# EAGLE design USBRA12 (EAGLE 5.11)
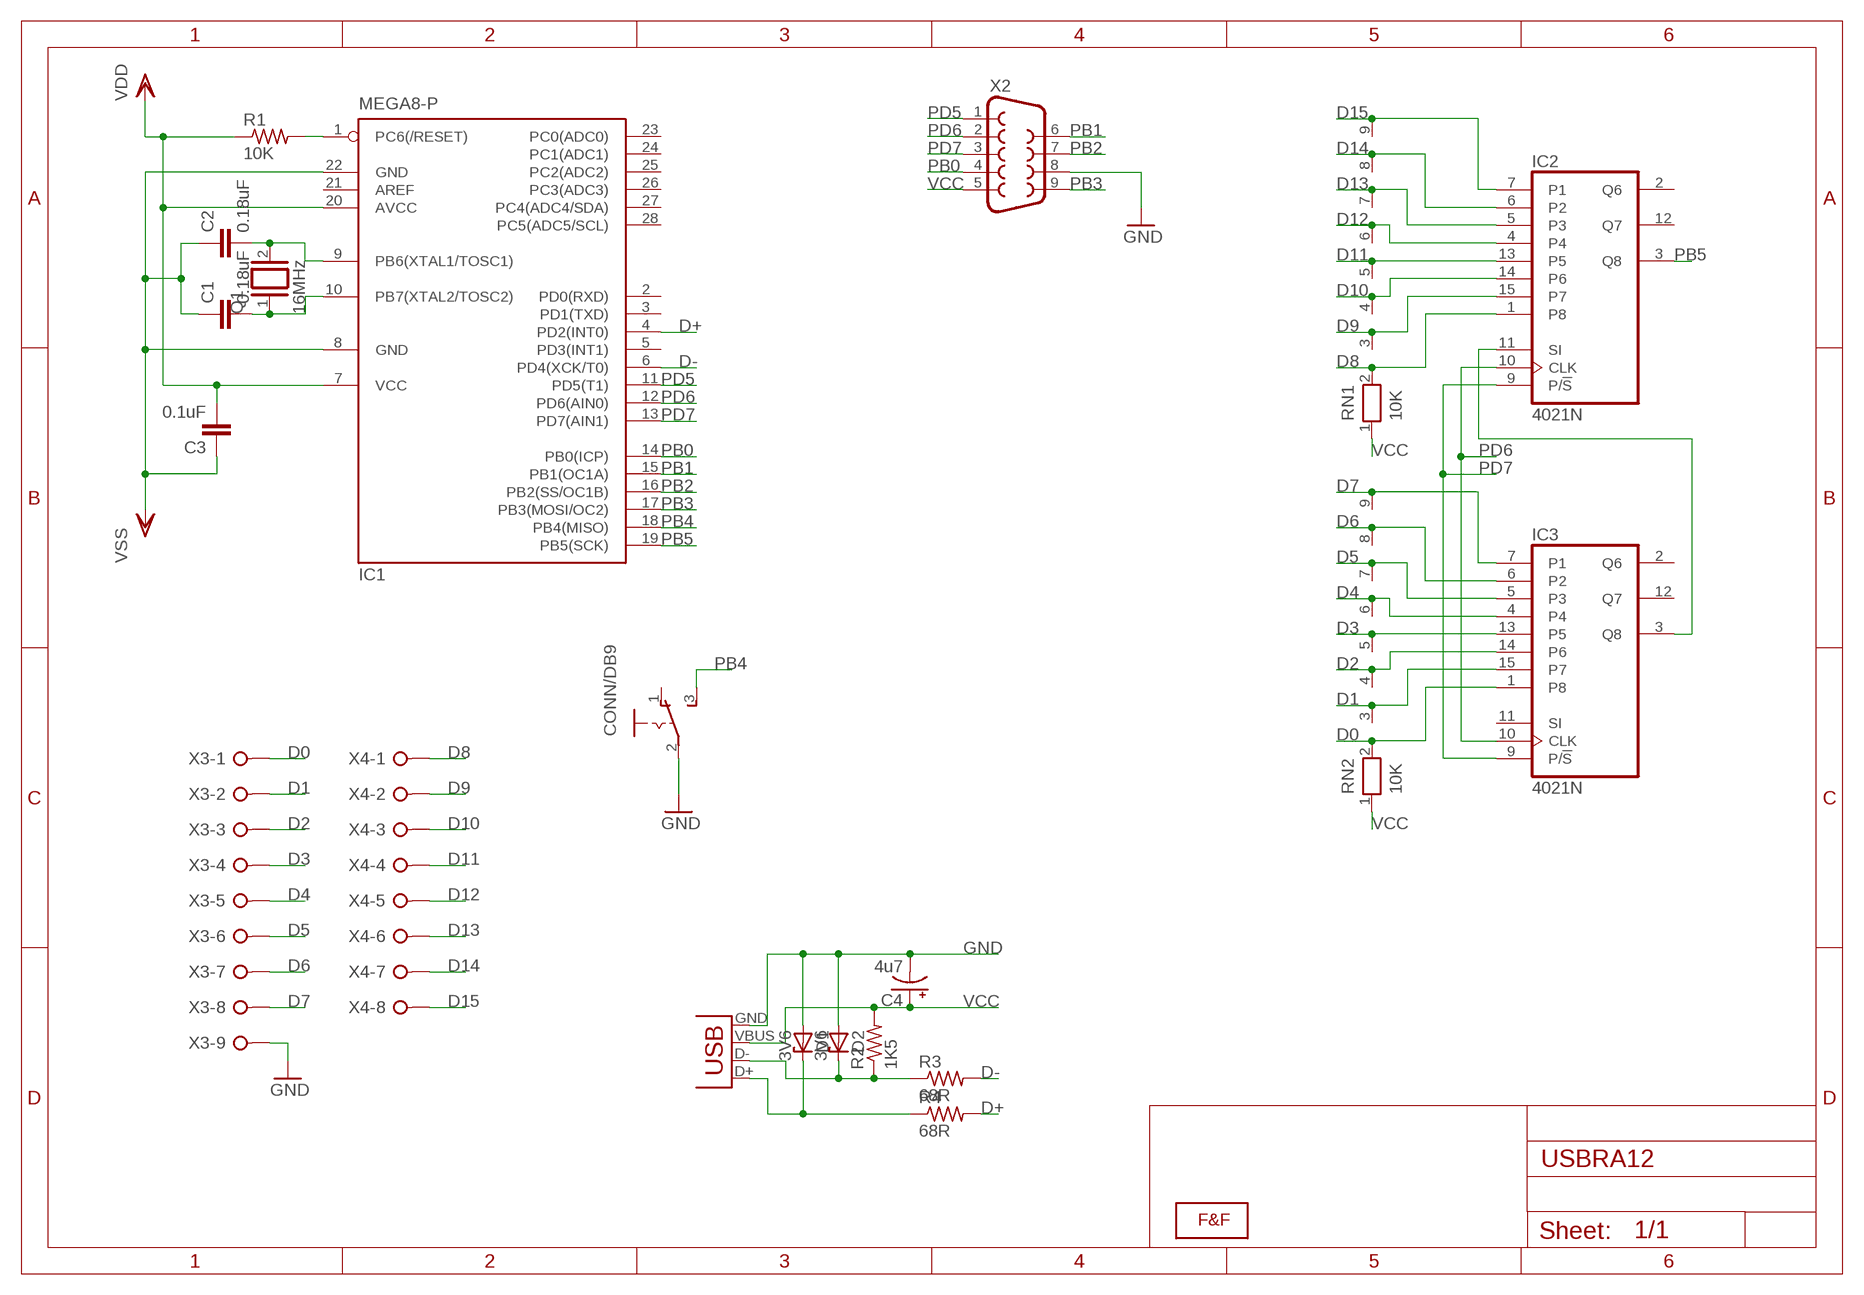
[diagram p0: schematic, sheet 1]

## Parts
C1  0.18uF  CAPPTH  [CAP-PTH-SMALL]
C2  0.18uF  CAPPTH  [CAP-PTH-SMALL]
C3  0.1uF  CAPPTH  [CAP-PTH-SMALL]
C4  4u7  CPOL-USE2.5-6  [E2,5-6]
CONN/DB9  CHAVE  [CHAVE]
D1  3V6  ZENER-DIODEF126-12  [F126Z12]
D2  3V6  ZENER-DIODEF126-12  [F126Z12]
IC1  MEGA8-P  [DIL28-3]
IC2  4021N  [DIL16]
IC3  4021N  [DIL16]
Q1  16MHz  XTAL/S  [QS]
R1  10K  R-US_0207/10  [0207/10]
R2  1K5  R-US_0207/10  [0207/10]
R3  68R  R-US_0207/10  [0207/10]
R4  68R  R-US_0207/10  [0207/10]
RN1  10K  RN08  [RN-9]
RN2  10K  RN08  [RN-9]
U$1  LOGOLOGO_WITHOUT_SMOKE_BIG  [LOGO2_BIG]
X1  USBPTH  [USB-B-PTH]
X2  DB9MALE  [DB9_MALE]
X3  W237-09P  [W237-9P]
X4  W237-08P  [W237-8P]

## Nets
D0: IC3.1(P8) RN2.2 X3.1
D1: IC3.15(P7) RN2.3 X3.2
D2: IC3.14(P6) RN2.4 X3.3
D3: IC3.13(P5) RN2.5 X3.4
D4: IC3.4 RN2.6 X3.5
D5: IC3.5(P3) RN2.7 X3.6
D6: IC3.6(P2) RN2.8 X3.7
D7: IC3.7(P1) RN2.9 X3.8
D8: IC2.1(P8) RN1.2 X4.1
D9: IC2.15(P7) RN1.3 X4.2
D10: IC2.14(P6) RN1.4 X4.3
D11: IC2.13(P5) RN1.5 X4.4
D12: IC2.4 RN1.6 X4.5
D13: IC2.5(P3) RN1.7 X4.6
D14: IC2.6(P2) RN1.8 X4.7
D15: IC2.7(P1) RN1.9 X4.8
D+: IC1.4(PD2(INT0)) R4.2
D-: IC1.6(PD4(XCK/T0)) R3.2
GND: C1.1 C2.1 C3.1 C4.- CONN/DB9.2(P) D1.A D2.A IC1.8(GND) IC1.22(GND) X1.GND X2.8 X3.9 ; supply symbol labelled VSS
N$1: IC1.1(PC6(/RESET)) R1.2
N$2: C2.2 IC1.9(PB6(XTAL1/TOSC1)) Q1.2
N$3: C1.2 IC1.10(PB7(XTAL2/TOSC2)) Q1.1
N$4: IC2.11(SI) IC3.3(Q8)
N$8: D1.C R4.1 X1.D+
N$9: D2.C R2.1 R3.1 X1.D-
PB0: IC1.14(PB0(ICP)) X2.4
PB1: IC1.15(PB1(OC1A)) X2.6
PB2: IC1.16(PB2(SS/OC1B)) X2.7
PB3: IC1.17(PB3(MOSI/OC2)) X2.9
PB4: CONN/DB9.3(S) IC1.18(PB4(MISO))
PB5: IC1.19(PB5(SCK)) IC2.3(Q8)
PD5: IC1.11(PD5(T1)) X2.1
PD6: IC1.12(PD6(AIN0)) IC2.10(CLK) IC3.10(CLK) X2.2
PD7: IC1.13(PD7(AIN1)) IC2.9(P/!S) IC3.9(P/!S) X2.3
VCC: C3.2 C4.+ IC1.7(VCC) IC1.20(AVCC) R1.1 R2.2 RN1.1 RN2.1 X1.VBUS X2.5 ; supply symbol labelled VDD
Unconnected: CONN/DB9.1(O) IC1.2(PD0(RXD)) IC1.3(PD1(TXD)) IC1.5(PD3(INT1)) IC1.21(AREF) IC1.23(PC0(ADC0)) IC1.24(PC1(ADC1)) IC1.25(PC2(ADC2)) IC1.26(PC3(ADC3)) IC1.27(PC4(ADC4/SDA)) IC1.28(PC5(ADC5/SCL)) IC2.2(Q6) IC2.12(Q7) IC3.2(Q6) IC3.11(SI) IC3.12(Q7)

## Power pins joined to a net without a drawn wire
GND: IC2.8(VSS) IC3.8(VSS)
VCC: IC2.16(VDD) IC3.16(VDD)

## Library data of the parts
C1-C3 = SparkFun:CAP: Capacitor
C4 = adafruit:CPOL-US: POLARIZED CAPACITOR, American symbol
CONN/DB9 = switch-fef:CHAVE: chave Verificar
D1 D2 = diode:ZENER-DIODE: Z-Diode
IC1 = atmel:MEGA8-P: MICROCONTROLLER 8 Kbytes FLASH, 1 kbytes SRAM, 512 bytes EEPROM, USART, 4-channel 10 bit ADC, 2-channel 8 bit ADC Pin compatible with Atmega48, ATMega88, ATMega168 Source: avr.lbr; OC_FARNELL: unknown; OC_NEWARK: unknown
IC2 IC3 = 40xx:4021: 8-bit static SHIFT REGISTER
Q1 = special:XTAL/S: CRYSTAL
R1-R4 = adafruit:R-US_: RESISTOR, American symbol
RN1 RN2 = resistor-net:RN08: RESISTOR NETWORK; OC_FARNELL: unknown; OC_NEWARK: unknown
U$1 = F&F:LOGO: Faísca e Fumaça Logo
X1 = SparkFun:USB: USB Connectors USB-B-PTH is fully proven SKU : PRT-00139 USB-miniB is fully proven SKU : PRT-00587 USB-A-PCB is untested. USB-A-H is throughly reviewed, but untested. Spark Fun Electronics SKU : PRT-00437 USB-B-SMT is throughly reviewed, but untested. Needs silkscreen touching up. USB-A-S has not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
X2 = SparkFun:DB9: DB9 Connector Standard DB9 (D-Sub 9) serial connector. Can be used for CAN bus as well as RS485 and RS232. Footprint production proven. Spark Fun Electronics SKU : PRT-00429
X3 = con-wago-508:W237-09P: WAGO SREW CLAMP; OC_FARNELL: unknown; OC_NEWARK: unknown
X4 = con-wago-508:W237-08P: WAGO SREW CLAMP; OC_FARNELL: unknown; OC_NEWARK: unknown

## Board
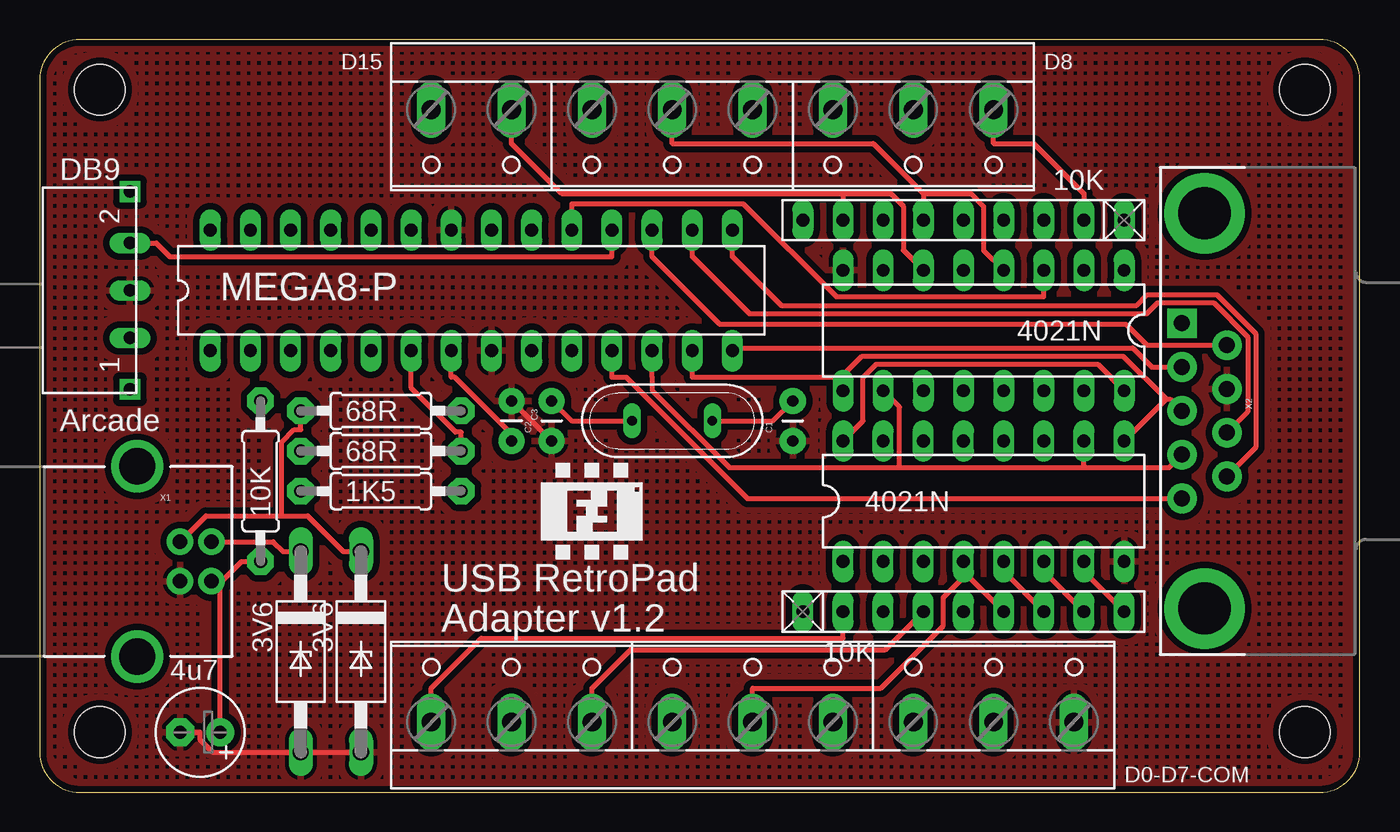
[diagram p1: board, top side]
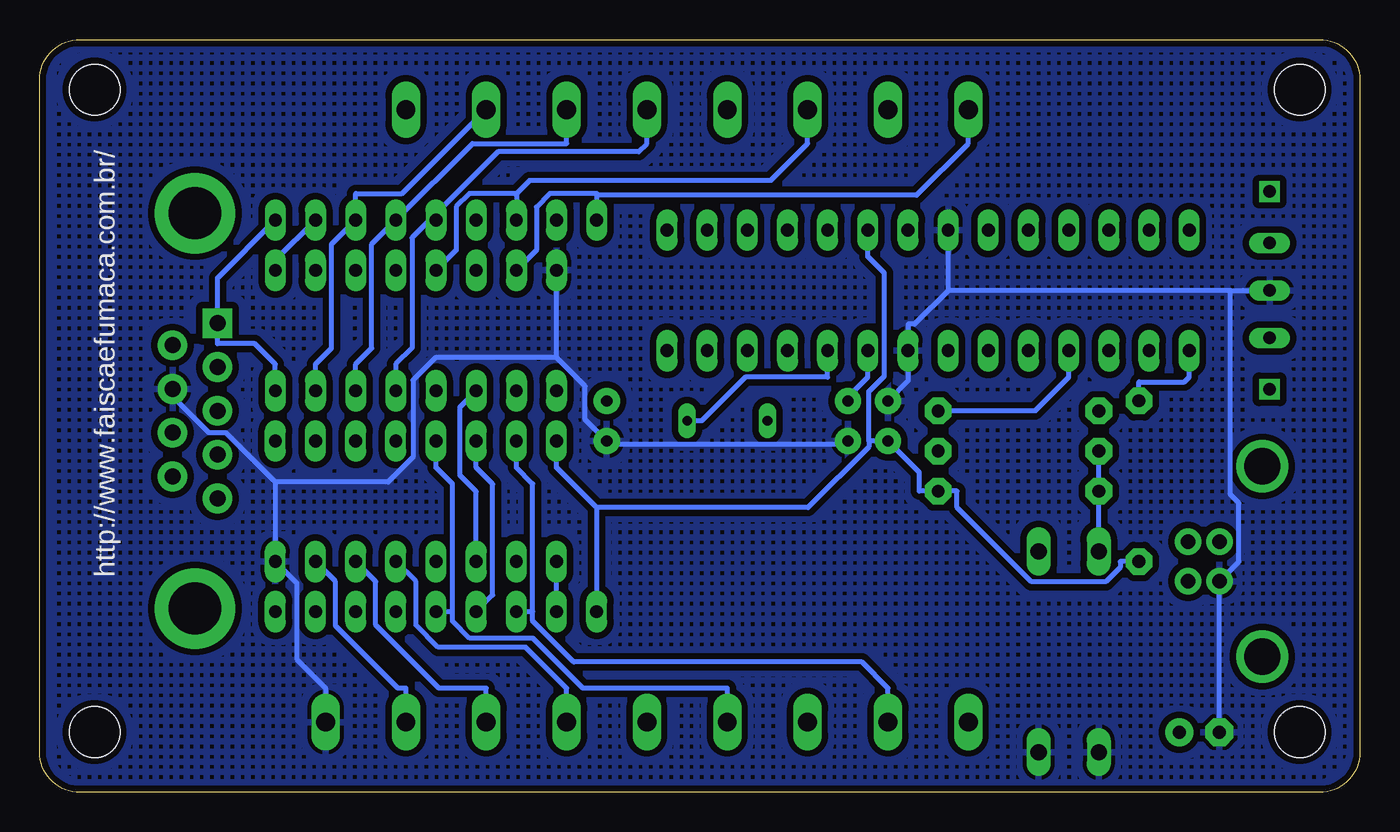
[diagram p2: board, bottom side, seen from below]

Size 83.49 x 47.62 mm. Coordinates in mm from the lower left corner, seen from the top.
Outline: 83.49,45.08 arc90 80.95,47.62 2.54,47.62 arc90 0,45.08 0,2.54 arc90 2.54,0 80.95,0 arc90 83.49,2.54 83.49,45.08
Copper layers (1*16): Top 0.035mm / dielectric 1.5mm / Bottom 0.035mm
Design rules "Fusion_eagle_rule_v1.1": minimum track width 6mil, minimum drill 12mil, track to track 6mil, track to pad 6mil, pad to pad 6mil, via to via 6mil, smd to smd 0mil, copper to edge 10mil, drill to drill 10mil, minimum pad ring 10mil, minimum via ring 6mil, stop-mask expansion 2mil, vias tented up to drill 100mil, thermal gap 10mil
Holes 3.2 mm at 3.81,44.45 3.81,3.81 80.01,44.45 80.01,3.81

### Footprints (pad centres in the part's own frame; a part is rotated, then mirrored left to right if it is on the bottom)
CAP-PTH-SMALL = drill 0.7 pad 1.651 round: 1 0,0; 2 2.54,0
E2,5-6 = drill 0.813 pad 1.778 round: + -1.27,0 | drill 0.813 pad 1.778 octagon: - 1.27,0
CHAVE = drill 0.8 long: 1 -3,0; 2 0,0; 3 3,0 | drill 0.8 square: P$1 -6.25,0; P$2 6.25,0
F126Z12 = drill 1.016 long: A 6.35,0; C -6.35,0
DIL28-3 = drill 0.813 long: 1 -16.51,-3.81; 2 -13.97,-3.81; 3 -11.43,-3.81; 4 -8.89,-3.81; 5 -6.35,-3.81; 6 -3.81,-3.81; 7 -1.27,-3.81; 8 1.27,-3.81; 9 3.81,-3.81; 10 6.35,-3.81; 11 8.89,-3.81; 12 11.43,-3.81; 13 13.97,-3.81; 14 16.51,-3.81; 15 16.51,3.81; 16 13.97,3.81; 17 11.43,3.81; 18 8.89,3.81; 19 6.35,3.81; 20 3.81,3.81; 21 1.27,3.81; 22 -1.27,3.81; 23 -3.81,3.81; 24 -6.35,3.81; 25 -8.89,3.81; 26 -11.43,3.81; 27 -13.97,3.81; 28 -16.51,3.81
DIL16 = drill 0.813 long: 1 -8.89,-3.81; 2 -6.35,-3.81; 3 -3.81,-3.81; 4 -1.27,-3.81; 5 1.27,-3.81; 6 3.81,-3.81; 7 6.35,-3.81; 8 8.89,-3.81; 9 8.89,3.81; 10 6.35,3.81; 11 3.81,3.81; 12 1.27,3.81; 13 -1.27,3.81; 14 -3.81,3.81; 15 -6.35,3.81; 16 -8.89,3.81
QS = drill 0.61 long: 1 -2.54,0; 2 2.54,0
0207/10 = drill 0.813 pad 1.676 octagon: 1 -5.08,0; 2 5.08,0
RN-9 = drill 0.813 long: 1 -10.16,0; 2 -7.62,0; 3 -5.08,0; 4 -2.54,0; 5 0,0; 6 2.54,0; 7 5.08,0; 8 7.62,0; 9 10.16,0
USB-B-PTH = drill 0.914 pad 1.676 round: D+ 0,1.25; D- 1.981,1.25; GND 0,-1.25; VBUS 1.981,-1.25 | drill 2.286 round: S1 -2.718,-6.02; S2 -2.718,6.02
DB9_MALE = drill 1.016 pad 1.88 round: 1 5.54,-1.42; 2 2.77,-1.42; 3 0,-1.42; 4 -2.77,-1.42; 6 4.15,1.42; 7 1.38,1.42; 8 -1.38,1.42; 9 -4.15,1.42 | drill 1.016 pad 1.88 square: 5 -5.54,-1.42 | drill 3.302 pad 5.08 round: G1 -12.5,0; G2 12.5,0
W237-9P = drill 1.194 long: 1 -20.32,-0.635; 2 -15.24,-0.635; 3 -10.16,-0.635; 4 -5.08,-0.635; 5 0,-0.635; 6 5.08,-0.635; 7 10.16,-0.635; 8 15.24,-0.635; 9 20.32,-0.635
W237-8P = drill 1.194 long: 1 -17.78,-0.635; 2 -12.7,-0.635; 3 -7.62,-0.635; 4 -2.54,-0.635; 5 2.54,-0.635; 6 7.62,-0.635; 7 12.7,-0.635; 8 17.78,-0.635

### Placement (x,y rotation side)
C1  47.62,22.23 90 top
C2  32.38,22.23 90 top
C3  29.84,24.77 270 top
C4  10.16,3.81 180 top
CONN/DB9  5.71,31.75 90 top
D1  20.32,8.89 270 top
D2  16.51,8.89 270 top
IC1  27.3,31.75 0 top
IC2  59.69,29.21 180 top
IC3  59.69,18.41 0 top
Q1  40.01,23.5 180 top
R1  13.97,19.68 90 top
R2  21.59,19.05 0 top
R3  21.59,21.59 0 top
R4  21.59,24.13 0 top
RN1  58.42,36.2 180 top
RN2  58.42,11.43 0 top
U$1  34.92,17.78 0 top
X1  8.89,14.61 0 top
X2  73.66,24.13 270 top
X3  45.09,5.08 0 top
X4  42.55,42.55 180 top

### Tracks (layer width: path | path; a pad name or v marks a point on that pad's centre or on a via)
D0
  Top 0.305: RN2.2 50.8,9.75 27.93,9.75 24.77,6.59 X3.1
  Bottom 0.305: RN2.2 IC3.1
D1
  Bottom 0.305: 52.31,11.43 RN2.3 | 52.31,11.43 52.31,10.83 49.73,8.25 31.5,8.25 29.84,6.59 X3.2 | 52.31,11.43 | 52.31,11.43 52.31,19.52 53.34,20.55 IC3.15
D2
  Top 0.305: X3.3 34.92,6.59 37.36,9.03 53.48,9.03 RN2.4
  Bottom 0.305: IC3.14 55.88,20.55 54.83,19.5 54.83,12.48 RN2.4
D3
  Bottom 0.305: X3.4 40.01,6.59 49.14,6.59 52.3,9.75 56.3,9.75 57.39,10.84 57.39,11.43 | 57.39,11.43 57.39,19.52 58.42,20.55 IC3.13 | 57.39,11.43 RN2.5
D4
  Top 0.305: 58.61,13.78 58.42,13.97 IC3.4 | 58.61,13.78 RN2.6 | 58.61,13.78 57.15,12.32 57.15,10.55 53.2,6.59 45.09,6.59 X3.5
D5
  Top 0.305: RN2.7 60.96,13.97 IC3.5
  Bottom 0.305: X3.6 50.16,6.59 52.75,9.18 58.28,9.18 59.69,10.59 59.69,13.34 IC3.5
D6
  Top 0.305: RN2.8 63.5,13.97 IC3.6
  Bottom 0.305: X3.7 55.24,6.59 58.23,6.59 62.23,10.59 62.23,13.34 IC3.6
D7
  Top 0.305: RN2.9 66.04,13.97 IC3.7
  Bottom 0.305: X3.8 60.33,6.59 60.82,6.59 64.77,10.54 64.77,13.34 IC3.7
D8
  Top 0.305: RN1.2 66.04,37.87 62.88,41.03 60.33,41.03 X4.1
  Bottom 0.305: RN1.2 68.58,33.66 IC2.1
D9
  Bottom 0.305: X4.2 60.55,37.87 63.5,37.87 RN1.3 65.02,34.67 65.02,28.09 66.04,27.08 IC2.15
D10
  Bottom 0.305: X4.3 50.16,41.03 56.12,41.03 RN1.4 62.48,34.67 62.48,28.09 63.5,27.08 IC2.14
D11
  Bottom 0.305: 58.42,36.6 54.5,40.51 45.6,40.51 45.09,41.03 X4.4 | IC2.13 60.96,27.08 59.94,28.09 59.94,35.07 58.42,36.6 | 58.42,36.6 RN1.5
D12
  Top 0.305: X4.5 40.01,41.03 52.72,41.03 55.88,37.87 | 55.88,37.87 RN1.6 | IC2.4 59.69,34.29 59.69,37.06 58.88,37.87 55.88,37.87
D13
  Bottom 0.305: 53.34,37.87 56.31,37.87 57.15,37.03 57.15,34.29 IC2.5 | 53.34,37.87 53.34,37.74 RN1.7 | X4.6 34.92,41.03 37.26,38.7 52.51,38.7 53.34,37.87
D14
  Top 0.305: 50.8,37.87 33.01,37.87 29.84,41.03 X4.7 | 50.8,37.87 53.82,37.87 54.61,37.08 54.61,34.29 IC2.6 | 50.8,37.87 50.8,37.74 RN1.8
D15
  Bottom 0.305: X4.8 24.77,41.03 28.03,37.77 48.26,37.77 | 48.26,37.77 48.26,37.87 51.23,37.87 52.07,37.03 52.07,34.29 IC2.7 | 48.26,37.77 RN1.9
D+
  Bottom 0.305: IC1.4 18.41,26.26 20.55,24.13 R4.2
D-
  Top 0.305: R3.2 26.67,22.78 26.3,22.78 23.5,25.59 IC1.6
GND
  Top 0.305: C4.- 10.13,3.81 10.13,3.34 10.94,2.54 D2.A D1.A | C3.1 C2.1
  Bottom 0.305: 8.19,31.75 7.38,31.75 CONN/DB9.2 | 8.19,31.75 26.04,31.75 | 8.19,31.75 8.19,18.84 7.66,18.3 7.66,14.59 X1.GND C4.- | C2.1 32.6,22.01 47.41,22.01 C1.1 48.98,23.58 48.98,25.69 50.8,27.5 | 26.04,31.75 26.04,33.88 IC1.22 | 26.04,31.75 28.17,29.62 28.57,29.62 IC1.8 28.57,26.04 C3.1 | 50.8,27.5 IC2.8 | 68.58,19.62 61.45,19.62 59.87,21.2 59.87,26.08 58.45,27.5 50.8,27.5 | 68.58,19.62 71.7,22.75 72.77,22.75 75.08,25.05 X2.8 | 68.58,19.62 IC3.8 67.23,13.26 67.23,8.42 65.41,6.59 X3.9
  pour Top (isolate 0.406, hatched): 0,46.99 83.82,46.99 83.82,0 0,0
  pour Bottom (isolate 0.406, hatched): 0,46.99 83.82,46.99 83.82,0 0,0
N$1
  Bottom 0.305: IC1.1 10.79,26.26 11.1,25.96 13.97,25.96 R1.2
N$2
  Top 0.305: Q1.2 33.66,23.5 C2.2
  Bottom 0.305: IC1.9 31.11,26.26 32.38,24.99 C2.2
N$3
  Top 0.305: Q1.1 46.35,23.5 C1.2
  Bottom 0.305: Q1.1 41.63,23.5 38.86,26.26 33.66,26.26 IC1.10
N$4
  Bottom 0.305: IC3.3 55.88,19.02 56.91,20.06 56.91,24.37 IC2.11
N$8
  Top 0.305: 15.3,17.49 16.95,17.49 19.2,15.24 D1.C | X1.D+ 10.52,17.49 15.3,17.49 | 15.3,17.49 15.3,22.13 16.11,22.94 16.51,22.94 R4.1
N$9
  Top 0.305: D2.C 15.39,15.24 14.78,15.86 X1.D-
  Bottom 0.305: D2.C R2.1 R3.1
PB0
  Top 0.305: IC1.14 43.98,28.11 69.12,28.11 70.33,26.9 X2.4
PB1
  Top 0.305: X2.6 76.9,21.8 76.9,29.02 74.45,31.48 70.05,31.48 69.37,30.79 46.91,30.79 43.81,33.88 IC1.15
PB2
  Top 0.305: IC1.16 41.27,33.88 44.88,30.28 70.01,30.28 70.69,30.97 74.24,30.97 76.39,28.81 76.39,24.06 X2.7
PB3
  Top 0.305: IC1.17 38.73,33.88 43,29.62 68.69,29.62 70.02,28.28 X2.9
PB4
  Top 0.305: CONN/DB9.3 7.38,34.75 8.24,33.88 36.2,33.88 IC1.18
PB5
  Top 0.305: IC1.19 33.66,37.24 44.48,37.24 50.38,31.34 63.5,31.34 IC2.3
PD5
  Top 0.305: X2.1 44.76,18.59 37.09,26.26 36.2,26.26 IC1.11
PD6
  Top 0.305: 54.37,20.55 43.61,20.55 38.73,25.43 38.73,26.26 IC1.12 | IC2.10 54.37,24.37 54.37,20.55 | 54.37,20.55 66.04,20.55 | 66.04,20.55 66.04,20.68 IC3.10 | X2.2 71.43,20.55 66.04,20.55
PD7
  Top 0.305: 71.23,24.88 IC3.9 | X2.3 71.49,24.88 71.23,24.88 | 71.23,24.88 68.51,27.6 52.01,27.6 50.8,26.38 | 50.8,26.38 50.68,26.26 41.27,26.26 IC1.13 | 50.8,26.38 IC2.9
VCC
  Top 0.305: 11.43,13.36 11.53,13.36 12.78,14.61 R1.1 | 11.43,13.36 X1.VBUS | C4.+ 11.43,13.36 | IC1.7 26.04,26.26 26.24,26.26 29.84,22.66 C3.2 | IC2.16 66.9,27.08 52.91,27.08 52.07,26.23 52.07,23.5 IC3.16
  Bottom 0.305: 31.05,22.23 C3.2 27.86,20.24 27.86,19.05 R2.2 25.48,19.05 25.48,18.03 20.76,13.32 16.08,13.32 15.16,14.23 15.16,14.61 R1.1 | 48.26,18.01 34.89,18.01 31.05,21.85 31.05,22.23 | 31.05,22.23 31.05,25.36 30.08,26.33 30.08,32.85 31.11,33.88 IC1.20 | 48.26,18.01 50.8,20.55 IC3.16 | 48.26,18.01 RN2.1 | IC2.16 68.58,27.08 69.88,28.38 72.24,28.38 X2.5 72.24,32.53 RN1.1

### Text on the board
tPlace: D15 | D8 | DB9 | Arcade | USB RetroPad | Adapter v1.2 | D0-D7-COM
bPlace: http://www.faiscaefumaca.com.br/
